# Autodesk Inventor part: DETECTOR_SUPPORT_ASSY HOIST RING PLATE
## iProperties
Shininess: 64.0
Length Units: 11272
Angle Units: 11279
Time Units: 11290
Mass Units: 11286
Length Display Precision: 3
Angle Display Precision: 2
Compacted: True
Part Number: DETECTOR_SUPPORT_ASSY HOIST RING PLATE
Document SubType Name: Modeling
Created: 2004-08
Designer: John Blackburn
Material: MILD_STEEL
Manufacturer: Standard
Standards Organization: Custom
Density: 0.0
Volumn: 0.0
Area: 0.0
PropertySet Name: Model Information
Control State: 0
Master: False
Checked Out: False
Author: John Blackburn
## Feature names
1. ExtrusionBlind1
2. AM_HOLE_SI0030_1 [Hole]
